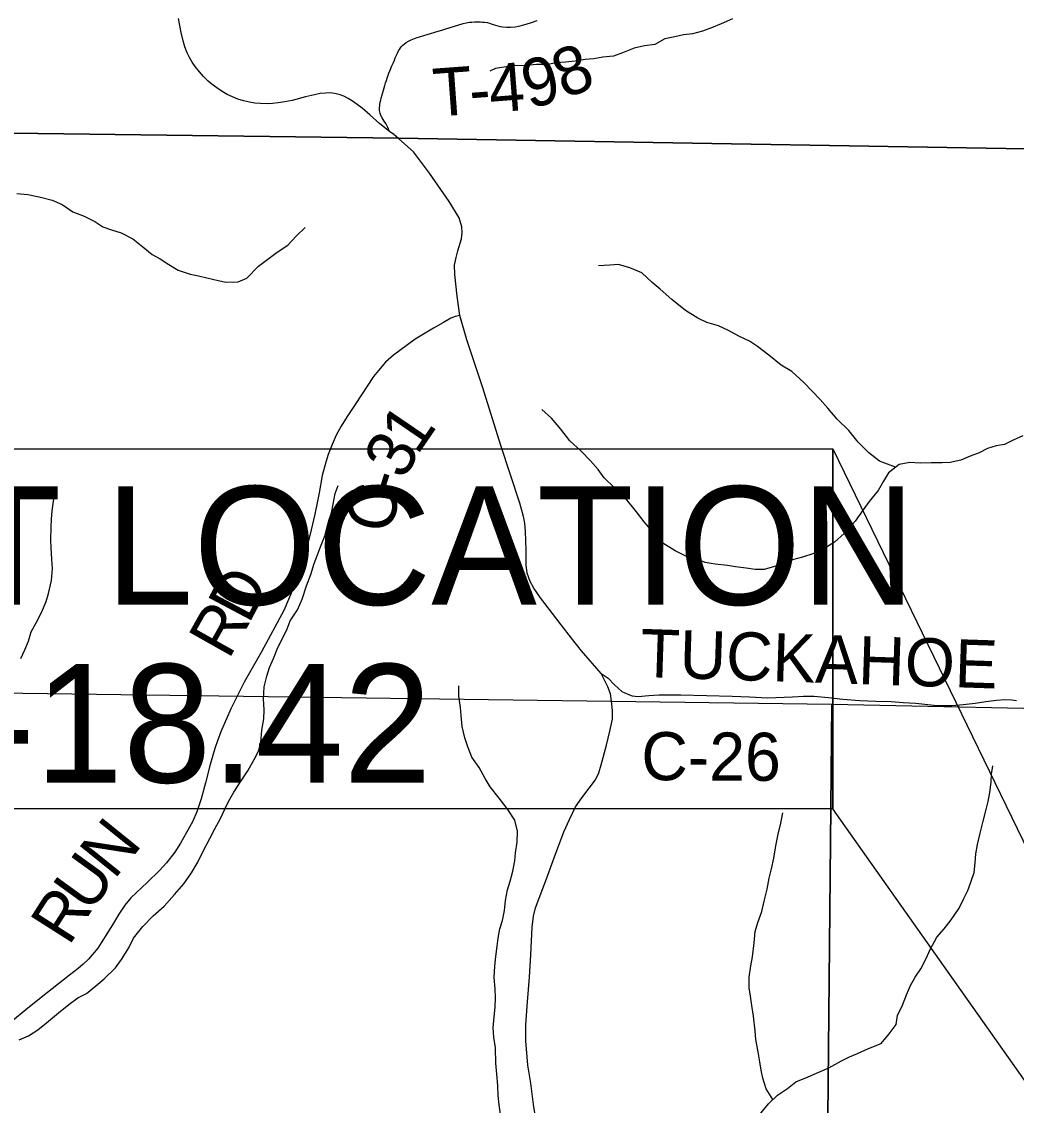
# Model space of a CAD drawing. Extents: x 0 to 34, y -8.9 to 22.
# Drawn here: x 25.769 to 26.944, y 10.789 to 12.069 of the extents above; entities that cross this region are included whole.
import ezdxf

# ---------------------------------------------------------------- set-up
doc = ezdxf.new("R2010")
doc.units = 0
for name, color, linetype in [('GM_X_Corporation', 7, 'Continuous'), ('GM_X_County_Road', 7, 'Continuous'), ('GM_X_County_Road_Text', 7, 'Continuous'), ('GM_X_Minor_River', 7, 'Continuous'), ('GM_X_State_Route', 7, 'Continuous'), ('GM_X_Township_Road', 7, 'Continuous'), ('GM_X_Township_Road_Text', 7, 'Continuous'), ('SH_Masking', 7, 'Continuous'), ('SH_Text', 7, 'Continuous')]:
    doc.layers.add(name, color=color, linetype=linetype)

msp = doc.modelspace()

# ---------------------------------------------------------------- linework, layer by layer
at = {"layer": 'GM_X_Corporation'}
for points in [[(28.8143, 13.904), (23.7167, 13.904), (23.7167, 11.9654), (24.1849, 11.9621), (24.2054, 11.9625), (24.3163, 11.9608), (25.0773, 11.948), (25.1035, 11.9505), (25.7218, 11.9377), (25.7578, 11.9372), (26.2139, 11.9314), (27.1396, 11.9157), (27.9423, 11.8981), (28.2591, 11.8967), (28.3241, 11.8942), (28.4085, 11.8914), (28.4711, 11.8911), (28.692, 11.888), (28.7762, 11.8872), (28.7779, 11.9899), (28.7786, 12.0342), (28.7787, 12.0377), (28.8049, 13.053), (28.8122, 13.7561)], [(28.8143, 13.904), (23.7167, 13.904), (23.7167, 11.9654), (24.1849, 11.9621), (24.2054, 11.9625), (24.3163, 11.9608), (25.0773, 11.948), (25.1035, 11.9505), (25.7218, 11.9377), (25.7578, 11.9372), (26.2139, 11.9314), (27.1396, 11.9157), (27.9423, 11.8981), (28.2591, 11.8967), (28.3241, 11.8942), (28.4085, 11.8914), (28.4711, 11.8911), (28.692, 11.888), (28.7762, 11.8872), (28.7779, 11.9899), (28.7786, 12.0342), (28.7787, 12.0377), (28.8049, 13.053), (28.8122, 13.7561)], [(25.7123, 11.2765), (26.7259, 11.2629), (26.7158, 10.2453), (25.698, 10.2614)], [(26.7259, 11.2629), (27.7448, 11.2414), (27.7275, 10.2275), (26.7158, 10.2453)]]:
    msp.add_lwpolyline(points, close=True, dxfattribs=at)
for points in [[(27.1396, 11.9157), (26.2139, 11.9314), (25.7578, 11.9372), (25.7218, 11.9377), (25.1035, 11.9505), (25.0773, 11.948), (24.3163, 11.9608), (24.2054, 11.9625), (24.1849, 11.9621), (23.7167, 11.9654), (23.7167, 7.104)], [(27.1396, 11.9157), (26.2139, 11.9314), (25.7578, 11.9372), (25.7218, 11.9377), (25.1035, 11.9505), (25.0773, 11.948), (24.3163, 11.9608), (24.2054, 11.9625), (24.2028, 11.8378), (24.2025, 11.824), (24.2007, 11.7362), (24.1845, 10.7587), (24.1844, 10.755), (24.1596, 9.2636)]]:
    msp.add_lwpolyline(points, dxfattribs=at)
at = {"layer": 'GM_X_County_Road'}
for points in [[(26.2863, 11.7218), (26.2809, 11.7208), (26.276, 11.7187), (26.2673, 11.7138), (26.2553, 11.7068), (26.2435, 11.6999), (26.2338, 11.6938), (26.2248, 11.6873), (26.208, 11.6749), (26.1989, 11.6666), (26.1903, 11.6568), (26.1845, 11.6499), (26.1629, 11.6167), (26.1533, 11.6025), (26.1462, 11.5911), (26.1405, 11.5806), (26.1356, 11.5696), (26.131, 11.5578), (26.1282, 11.5486), (26.1241, 11.5327), (26.1202, 11.5124), (26.1183, 11.5025), (26.1151, 11.4873), (26.1093, 11.462), (26.1052, 11.4455), (26.0975, 11.4196), (26.0897, 11.3993), (26.0785, 11.3734), (26.0521, 11.3248), (26.0319, 11.2886), (26.0162, 11.2572), (26.0111, 11.2456), (26.0051, 11.232), (26.0006, 11.2205), (25.9973, 11.2106), (25.9918, 11.1914), (25.9863, 11.1698), (25.9812, 11.151), (25.9759, 11.1357), (25.9708, 11.1237), (25.9565, 11.0987), (25.9501, 11.0881), (25.9402, 11.0754), (25.9318, 11.0664), (25.9172, 11.0521), (25.898, 11.034), (25.891, 11.0252), (25.8838, 11.0146), (25.8774, 11.0043), (25.8704, 10.9928), (25.8631, 10.981), (25.8589, 10.9747), (25.8481, 10.9616), (25.8417, 10.9556), (25.8357, 10.9507), (25.8256, 10.9428), (25.7923, 10.9162), (25.7739, 10.9017), (25.7586, 10.889)], [(26.4532, 11.299), (26.4615, 11.2936), (26.4693, 11.2856), (26.4779, 11.2776), (26.4849, 11.2747), (26.4901, 11.2728), (26.4969, 11.272), (26.5098, 11.2732), (26.522, 11.2737), (26.5473, 11.2737), (26.6082, 11.2721), (26.6285, 11.2715), (26.6497, 11.2702), (26.6795, 11.2715), (26.6924, 11.2721), (26.7048, 11.2721), (26.7219, 11.2706), (26.7386, 11.2685), (26.759, 11.2671), (26.7777, 11.2665), (26.7957, 11.2658), (26.81, 11.2649), (26.8251, 11.2639), (26.8463, 11.2618), (26.8558, 11.2612), (26.8673, 11.2611), (26.881, 11.2625), (26.8949, 11.2641), (26.9077, 11.266), (26.9203, 11.2676), (26.93, 11.2682), (26.9383, 11.2678), (26.9437, 11.2671)]]:
    msp.add_lwpolyline(points, dxfattribs=at)
at = {"layer": 'GM_X_Minor_River'}
for points in [[(26.6083, 12.0724), (26.5952, 12.0662), (26.5838, 12.0615), (26.5729, 12.0579), (26.5612, 12.0547), (26.5506, 12.0535), (26.5404, 12.0511), (26.5284, 12.0486), (26.5167, 12.042), (26.5046, 12.0404), (26.4925, 12.0376), (26.4786, 12.0321), (26.468, 12.0282), (26.4555, 12.0272), (26.4446, 12.0252), (26.4344, 12.0243), (26.4227, 12.0223), (26.4113, 12.021), (26.4004, 12.0205), (26.3905, 12.0185), (26.3769, 12.0183), (26.3656, 12.017), (26.3512, 12.0168), (26.3414, 12.0156), (26.3285, 12.0135), (26.3218, 12.0104)], [(25.7633, 11.866), (25.7762, 11.8649), (25.7898, 11.8622), (25.805, 11.8581), (25.8168, 11.8528), (25.8297, 11.8445), (25.843, 11.8393), (25.8555, 11.8328), (25.865, 11.8268), (25.8753, 11.823), (25.8867, 11.8197), (25.9004, 11.8125), (25.9122, 11.803), (25.9232, 11.794), (25.9327, 11.7887), (25.9429, 11.7822), (25.954, 11.7754), (25.968, 11.7706), (25.9779, 11.7687), (25.9877, 11.7664), (26.001, 11.7631), (26.0105, 11.7612), (26.0249, 11.7616), (26.0348, 11.7658), (26.0488, 11.78), (26.0583, 11.7872), (26.0708, 11.7967), (26.0833, 11.8051), (26.0931, 11.8154), (26.1037, 11.8257)], [(26.8011, 11.5426), (26.7821, 11.5499), (26.7695, 11.5598), (26.757, 11.5723), (26.7459, 11.5859), (26.7322, 11.5995), (26.7212, 11.6124), (26.7121, 11.6226), (26.7026, 11.6325), (26.6927, 11.6427), (26.6786, 11.6556), (26.6661, 11.6631), (26.6512, 11.6752), (26.6379, 11.6851), (26.6284, 11.6915), (26.6159, 11.6975), (26.6037, 11.704), (26.592, 11.7096), (26.5783, 11.7137), (26.5676, 11.7186), (26.5528, 11.7277), (26.5369, 11.7406), (26.5232, 11.7531), (26.5137, 11.761), (26.5015, 11.7724), (26.4874, 11.778), (26.4738, 11.7821), (26.4635, 11.7814), (26.4503, 11.7806)], [(26.9512, 11.5797), (26.9399, 11.5748), (26.9296, 11.5694), (26.9198, 11.5679), (26.9095, 11.5648), (26.8997, 11.5598), (26.8891, 11.5556), (26.8781, 11.551), (26.8656, 11.5483), (26.8561, 11.5479), (26.8432, 11.5478), (26.8299, 11.5474), (26.8177, 11.5481), (26.8052, 11.5458), (26.7927, 11.5359), (26.7867, 11.526), (26.7803, 11.5153), (26.77, 11.502), (26.7629, 11.4925), (26.7534, 11.4788), (26.7405, 11.4643), (26.7288, 11.454), (26.7163, 11.4464), (26.7034, 11.4402), (26.6913, 11.4364), (26.6792, 11.4333), (26.6697, 11.4291), (26.6579, 11.4253), (26.6458, 11.4218), (26.6352, 11.4218), (26.6245, 11.4236), (26.612, 11.4251), (26.6025, 11.4266), (26.5881, 11.4281), (26.5763, 11.4303), (26.5657, 11.4345), (26.5532, 11.4375), (26.5406, 11.4439), (26.5262, 11.453), (26.5144, 11.4662), (26.5041, 11.478), (26.495, 11.4901), (26.482, 11.506), (26.4691, 11.5185), (26.4569, 11.5302), (26.4497, 11.5401), (26.4406, 11.5503), (26.4299, 11.5617), (26.4162, 11.5738), (26.4056, 11.5878), (26.3949, 11.6007), (26.3835, 11.6109)], [(26.0776, 11.3413), (26.0825, 11.3519), (26.0863, 11.3614), (26.095, 11.3744), (26.1002, 11.3869), (26.1055, 11.4025), (26.1104, 11.4158), (26.1146, 11.4288), (26.1183, 11.439), (26.1221, 11.4486), (26.1274, 11.4626), (26.1304, 11.4737), (26.1349, 11.4889), (26.1371, 11.4991), (26.1394, 11.5117), (26.1428, 11.5212)], [(25.768, 11.3167), (25.7729, 11.3269), (25.7771, 11.3372), (25.7805, 11.3482), (25.7861, 11.3589), (25.7926, 11.3711), (25.7982, 11.384), (25.8008, 11.3935), (25.8042, 11.4087), (25.8053, 11.4232), (25.8049, 11.4342), (25.8041, 11.4475), (25.8037, 11.457), (25.8041, 11.4718), (25.8044, 11.4813), (25.8052, 11.4912), (25.8066, 11.5026), (25.8096, 11.5159)], [(25.7661, 10.8664), (25.7771, 10.871), (25.7881, 10.8783), (25.7983, 10.8863), (25.8124, 10.8981), (25.8248, 10.908), (25.8355, 10.916), (25.8457, 10.921), (25.8567, 10.9302), (25.8665, 10.9382), (25.8798, 10.9515), (25.8869, 10.961), (25.8956, 10.9751), (25.9013, 10.9865), (25.9123, 11.0003), (25.9244, 11.0128), (25.9372, 11.0243), (25.9497, 11.038), (25.9607, 11.0506), (25.9698, 11.0635), (25.977, 11.0761), (25.9838, 11.0898), (25.9913, 11.1043), (25.9973, 11.1157), (26.0038, 11.1279), (26.0087, 11.1381), (26.0132, 11.148), (26.0196, 11.1587), (26.0276, 11.1712), (26.0363, 11.1842), (26.0438, 11.1975), (26.0487, 11.2074), (26.0517, 11.2173), (26.0528, 11.2321), (26.0551, 11.2454), (26.0554, 11.2561), (26.0546, 11.269), (26.0553, 11.2834), (26.0584, 11.296), (26.0617, 11.3062), (26.0663, 11.3169), (26.0715, 11.3298), (26.0776, 11.3413)], [(26.3344, 10.7786), (26.3329, 10.7896), (26.3317, 10.8006), (26.3313, 10.8124), (26.3301, 10.8257), (26.329, 10.8386), (26.3285, 10.8568), (26.3266, 10.8694), (26.3258, 10.8804), (26.3269, 10.8933), (26.3284, 10.9047), (26.3287, 10.9165), (26.3283, 10.9264), (26.3272, 10.9401), (26.3279, 10.9534), (26.329, 10.9648), (26.3305, 10.9769), (26.3316, 10.9864), (26.3338, 10.9975), (26.3369, 11.0074), (26.3391, 11.0191), (26.3406, 11.0309), (26.3428, 11.0435), (26.3458, 11.0537), (26.3492, 11.0655), (26.3515, 11.0777), (26.3522, 11.0872), (26.3541, 11.0998), (26.3544, 11.1127), (26.3513, 11.1256), (26.343, 11.1385), (26.3331, 11.1517), (26.3224, 11.165), (26.3163, 11.1749), (26.3094, 11.1878), (26.3007, 11.2003), (26.2961, 11.2124), (26.2923, 11.223), (26.2892, 11.2363), (26.288, 11.2493), (26.2873, 11.2588), (26.2853, 11.2724), (26.2853, 11.2846)], [(26.6403, 10.7777), (26.6509, 10.7906), (26.6615, 10.8009), (26.6736, 10.8089), (26.6834, 10.8166), (26.6978, 10.8227), (26.7077, 10.8269), (26.7221, 10.8334), (26.7372, 10.8414), (26.7467, 10.8464), (26.7562, 10.8502), (26.7691, 10.856), (26.7839, 10.8621), (26.7933, 10.8735), (26.8016, 10.8846), (26.8035, 10.8952), (26.8092, 10.9074), (26.8141, 10.9196), (26.8186, 10.9306), (26.8243, 10.9405), (26.8307, 10.9501), (26.8371, 10.9622), (26.842, 10.9729), (26.8499, 10.9874), (26.8583, 10.9973), (26.8666, 11.0079), (26.876, 11.022), (26.8813, 11.0323), (26.8862, 11.0426), (26.89, 11.0525), (26.8937, 11.0639), (26.8952, 11.0753), (26.896, 11.0859), (26.8978, 11.097), (26.9008, 11.1103), (26.9046, 11.1244), (26.908, 11.1384), (26.9102, 11.1479), (26.9125, 11.1586), (26.914, 11.1708), (26.9143, 11.1803), (26.9158, 11.1898)], [(26.6562, 10.7958), (26.6482, 10.8085), (26.6443, 10.821), (26.6424, 10.8305), (26.6405, 10.8427), (26.6386, 10.8521), (26.6362, 10.8666), (26.6351, 10.8768), (26.6331, 10.8943), (26.6312, 10.9068), (26.6297, 10.9179), (26.6281, 10.9277), (26.6281, 10.9403), (26.6303, 10.9536), (26.6322, 10.9642), (26.634, 10.981), (26.6351, 10.9943), (26.6382, 11.0049), (26.6431, 11.0179), (26.6457, 11.03), (26.6494, 11.0441), (26.6517, 11.0574), (26.6547, 11.0684), (26.6573, 11.081), (26.6595, 11.0954), (26.6625, 11.1091), (26.6655, 11.1224), (26.6678, 11.1346)]]:
    msp.add_lwpolyline(points, dxfattribs=at)
at = {"layer": 'GM_X_State_Route'}
for points in [[(26.2034, 11.9394), (26.2019, 11.9405), (26.1918, 11.9488), (26.1801, 11.959), (26.1712, 11.9667), (26.1654, 11.9713), (26.1599, 11.9751), (26.1546, 11.9783), (26.1497, 11.9808), (26.1452, 11.9826), (26.1404, 11.9838), (26.1363, 11.9844), (26.1326, 11.9847), (26.1277, 11.9845), (26.1217, 11.9839), (26.115, 11.9826), (26.1042, 11.98), (26.0885, 11.976), (26.0799, 11.9742), (26.0719, 11.9729), (26.0651, 11.9723), (26.0588, 11.972), (26.0513, 11.9722), (26.0444, 11.9728), (26.0382, 11.9737), (26.0309, 11.9754), (26.0244, 11.9776), (26.018, 11.9801), (26.0118, 11.9831), (26.0058, 11.9865), (25.9995, 11.9906), (25.994, 11.9947), (25.9893, 11.9988), (25.984, 12.0041), (25.979, 12.0097), (25.974, 12.0161), (25.9705, 12.0212), (25.9674, 12.0266), (25.9646, 12.0323), (25.9619, 12.0393), (25.9597, 12.0465), (25.9573, 12.0562), (25.9541, 12.0726)], [(26.2141, 11.9309), (26.2084, 11.9356), (26.2034, 11.9394)], [(26.3783, 10.7611), (26.3736, 10.79), (26.3703, 10.8152), (26.3667, 10.8364), (26.3645, 10.8651), (26.3644, 10.8841), (26.3663, 10.9113), (26.3688, 10.9402), (26.3704, 10.9668), (26.3719, 10.9992), (26.3736, 11.0123), (26.3759, 11.0222), (26.3889, 11.0563), (26.3981, 11.0823), (26.4092, 11.112), (26.4161, 11.1267), (26.4231, 11.1417), (26.4307, 11.1523), (26.4466, 11.1734), (26.4506, 11.1818), (26.4534, 11.191), (26.4597, 11.2144), (26.4638, 11.231), (26.4666, 11.245), (26.4666, 11.2554), (26.4656, 11.2662), (26.4644, 11.2749), (26.4614, 11.2831), (26.4532, 11.299), (26.43, 11.3259), (26.4182, 11.3406), (26.4062, 11.3563), (26.3816, 11.3882), (26.3737, 11.3999), (26.3695, 11.4075), (26.3662, 11.4177), (26.3649, 11.4273), (26.3647, 11.4446), (26.3641, 11.4666), (26.3633, 11.4765), (26.3618, 11.4845), (26.3574, 11.5001), (26.3351, 11.5683), (26.3135, 11.6364), (26.2999, 11.6776), (26.2946, 11.693), (26.2863, 11.7218), (26.2832, 11.7447), (26.2805, 11.7702), (26.2803, 11.7815), (26.282, 11.7903), (26.2843, 11.7983), (26.2883, 11.8125), (26.2893, 11.8194), (26.2888, 11.8265), (26.2858, 11.8371), (26.2739, 11.8567), (26.2505, 11.8901), (26.2316, 11.9151), (26.2215, 11.9242), (26.2141, 11.9309)]]:
    msp.add_lwpolyline(points, dxfattribs=at)
at = {"layer": 'GM_X_Township_Road'}
msp.add_lwpolyline([(26.2034, 11.9394), (26.2014, 11.9439), (26.2005, 11.9457), (26.199, 11.9485), (26.1971, 11.9516), (26.1947, 11.9552), (26.1933, 11.958), (26.1923, 11.9609), (26.1918, 11.9639), (26.1917, 11.9656), (26.1917, 11.9676), (26.1919, 11.9694), (26.1921, 11.9713), (26.1926, 11.9737), (26.1932, 11.9762), (26.1937, 11.9784), (26.1948, 11.9824), (26.1956, 11.9854), (26.1963, 11.9879), (26.1971, 11.9908), (26.1979, 11.9934), (26.1989, 11.9968), (26.1998, 11.9996), (26.2007, 12.0024), (26.2015, 12.0047), (26.2028, 12.0081), (26.2042, 12.0116), (26.2062, 12.0168), (26.208, 12.0207), (26.2092, 12.0236), (26.2103, 12.0263), (26.2116, 12.0293), (26.2128, 12.0316), (26.2141, 12.0343), (26.2153, 12.036), (26.2165, 12.0379), (26.2177, 12.0396), (26.2193, 12.0412), (26.2211, 12.0428), (26.223, 12.0444), (26.2257, 12.0459), (26.229, 12.0476), (26.2348, 12.0498), (26.2479, 12.0538), (26.2609, 12.0578), (26.2651, 12.059), (26.2699, 12.0604), (26.284, 12.0649), (26.2906, 12.0668), (26.2939, 12.0676), (26.296, 12.0679), (26.298, 12.0682), (26.3008, 12.0684), (26.3037, 12.0686), (26.3069, 12.0687), (26.3109, 12.0686), (26.3133, 12.0685), (26.3158, 12.0683), (26.3186, 12.0679), (26.3215, 12.0671), (26.3234, 12.0665), (26.3259, 12.0657), (26.3312, 12.0641), (26.334, 12.0633), (26.3371, 12.0627), (26.3418, 12.0624), (26.3465, 12.0624), (26.3519, 12.0628), (26.3561, 12.0635), (26.3621, 12.0651), (26.3698, 12.0674), (26.378, 12.0704)], dxfattribs=at)
at = {"layer": 'SH_Masking'}
msp.add_lwpolyline([(24.9369, 11.5643), (26.727, 11.5643), (26.727, 11.1393), (24.9369, 11.1393)], close=True, dxfattribs=at)
at = {"layer": 'SH_Text'}
for points in [[(26.727, 11.1393), (24.9369, 11.1393), (24.9369, 11.5643), (26.727, 11.5643)], [(27.3869, 10.2045), (26.727, 11.1393), (26.727, 11.5643)]]:
    msp.add_lwpolyline(points, close=True, dxfattribs=at)

# ---------------------------------------------------------------- texts
at = {"layer": 'GM_X_County_Road_Text'}
for s, height, rotation, p in [('1', 0.0568, 55.6662, (26.2361, 11.5558)), ('3', 0.0568, 61.9826, (26.2206, 11.5263)), ('-', 0.0568, 72.5426, (26.2146, 11.5066)), ('C', 0.0568, 77.8924, (26.2052, 11.4624)), ('D', 0.0568, 62.048, (26.0371, 11.3564)), ('R', 0.0568, 60.6516, (26.0135, 11.3144)), ('TUCKAHOE', 0.05682, 358.1241, (26.4989, 11.295)), ('C-26', 0.05682, 359.6571, (26.5007, 11.1731)), ('N', 0.0568, 51.1217, (25.8782, 11.0546)), ('U', 0.0568, 54.0947, (25.8494, 11.0147)), ('R', 0.0568, 57.4932, (25.8248, 10.9761))]:
    msp.add_text(s, height=height, rotation=rotation, dxfattribs=at).set_placement(p)
at = {"layer": 'GM_X_Township_Road_Text'}
for s, rotation, p in [('8', 22.4005, (26.4104, 11.9772)), ('4', 4.4909, (26.3228, 11.9614)), ('9', 14.0921, (26.3679, 11.9658)), ('T', 4.1885, (26.2568, 11.9566)), ('-', 4.2457, (26.2993, 11.9597))]:
    msp.add_text(s, height=0.0568, rotation=rotation, dxfattribs=at).set_placement(p)
at = {"layer": 'SH_Text'}
for s, p in [('PROJECT LOCATION', (24.942, 11.3802)), ('NOB-147-18.42', (24.942, 11.1702))]:
    msp.add_text(s, height=0.14, dxfattribs=at).set_placement(p)

doc.saveas('drawing.dxf')
